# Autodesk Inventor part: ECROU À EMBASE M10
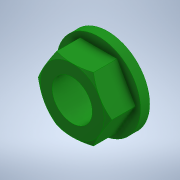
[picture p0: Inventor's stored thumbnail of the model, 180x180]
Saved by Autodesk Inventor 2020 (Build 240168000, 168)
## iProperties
Created: 2003-06
Part Number: ECROU À EMBASE M10
Material: Générique
Document SubType Name: Modeling
Designer: Bruno
Density: 1 g/cm^3
Appearance: Par défaut
Author: Bruno
Sending System: SolidWorks 2011
Last Author: Professeur
Last Saved: 2014-11-10
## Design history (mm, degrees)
feature "Enlèv. mat.-Extru.1"
node "Solide1"
